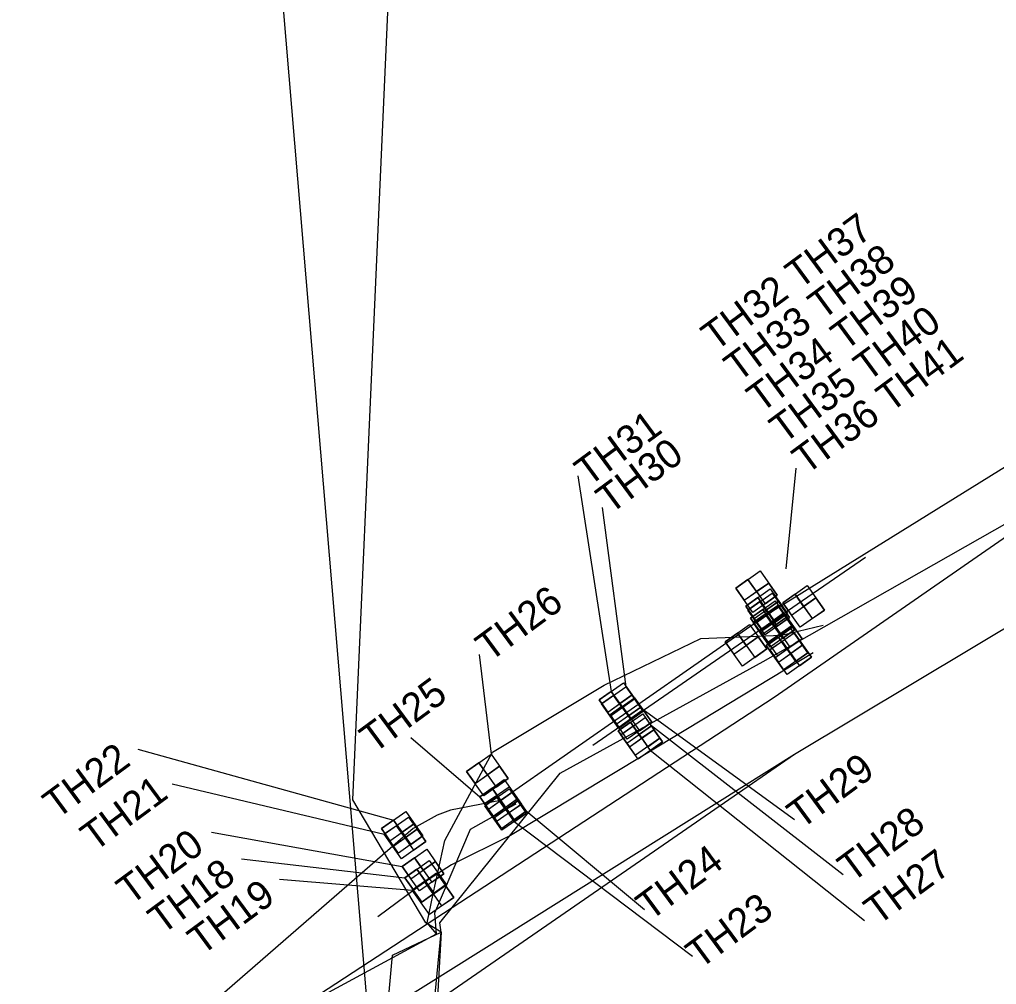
# Model space of a CAD drawing. Extents: x 507915 to 518914, y 880723 to 883087.
# Drawn here: x 509177.3 to 509259.1, y 882249.9 to 882330.6 of the extents above; entities that cross this region are included whole.
import ezdxf

# ---------------------------------------------------------------- set-up
doc = ezdxf.new("R2010")
doc.units = 0
for name, color, linetype in [('Driveway_ep', 7, 'Continuous'), ('GuardrailLt_ep', 7, 'Continuous'), ('GuardrailRt_ep', 7, 'Continuous'), ('Luminaire', 7, 'Continuous'), ('Miscellaneous3', 7, 'Continuous'), ('PavtAsphalt_ep', 7, 'Continuous'), ('PMBikeLane_ep', 7, 'Continuous'), ('PMNORTH_ep', 7, 'Continuous'), ('PoleLight_ep', 7, 'Continuous')]:
    doc.layers.add(name, color=color, linetype=linetype)

msp = doc.modelspace()

# ---------------------------------------------------------------- linework, layer by layer
at = {"layer": 'Driveway_ep'}
msp.add_lwpolyline([(509470.151, 882412.294), (509450.235, 882402.261), (509403.864, 882379.797), (509373.735, 882360.535), (509360.257, 882353.193), (509318.085, 882328.858), (509274.108, 882302.037), (509240.021, 882280.899), (509217.599, 882265.284), (509213.419, 882264.477), (509212.298, 882264.042), (509210.283, 882262.924), (509172.924, 882230.488), (509113.967, 882188.988), (509087.108, 882169.954), (509067.759, 882154.568), (509006.28, 882108.596)], dxfattribs=at)
at = {"layer": 'GuardrailRt_ep'}
for p, q in [((509224.055, 882292.462), (509226.858, 882274.411)), ((509242.3, 882293.092), (509241.454, 882284.664)), ((509226.084, 882289.794), (509228.078, 882274.796)), ((509215.795, 882277.487), (509216.795, 882269.158)), ((509242.196, 882263.663), (509229.521, 882272.862)), ((509246.255, 882259.069), (509230.211, 882271.523)), ((509210.078, 882270.556), (509215.857, 882265.584)), ((509187.249, 882269.577), (509208.641, 882263.643)), ((509248.039, 882255.209), (509230.12, 882269.461)), ((509190.117, 882266.683), (509207.86, 882262.449)), ((509229.625, 882256.117), (509219.745, 882264.387)), ((509233.648, 882252.217), (509218.733, 882263.502)), ((509193.411, 882262.634), (509209.374, 882259.752)), ((509195.914, 882260.382), (509209.579, 882258.809)), ((509199.094, 882258.69), (509210.202, 882257.772))]:
    msp.add_line(p, q, dxfattribs=at)
at = {"layer": 'Luminaire'}
msp.add_lwpolyline([(509209.542, 882030.607), (509208.49, 882117.664), (509208.133, 882156.35), (509208.412, 882184.48), (509208.186, 882227.958), (509206.41, 882248.671), (509195.558, 882377.683), (509191.832, 882422.316), (509185.306, 882558.4)], dxfattribs=at)
at = {"layer": 'Miscellaneous3'}
for points in [[(509130.876, 882181.709), (509131.052, 882184.291), (509136.669, 882194.388), (509176.072, 882223.491), (509242.192, 882269.149), (509301.705, 882304.805), (509379.728, 882350.734), (509420.133, 882372.958), (509456.8, 882391.955), (509476.67, 882399.785)], [(509130.876, 882181.709), (509131.052, 882184.291), (509136.669, 882194.388), (509176.072, 882223.491), (509204.835, 882245.757), (509242.192, 882269.149), (509301.705, 882304.805), (509379.728, 882350.734), (509420.133, 882372.958), (509456.8, 882391.955), (509476.67, 882399.785)]]:
    msp.add_lwpolyline(points, dxfattribs=at)
at = {"layer": 'PavtAsphalt_ep'}
for points in [[(509213.58, 882113.608), (509213.174, 882115.678), (509214.272, 882140.381), (509214.048, 882192.03), (509209.447, 882233.648), (509207.929, 882245.59), (509208.548, 882252.334), (509212.627, 882254.268), (509211.346, 882255.034), (509205.243, 882265.325), (509209.207, 882354.521), (509209.439, 882393.982), (509208.915, 882404.218), (509206.519, 882409.455), (509204.896, 882411.033)], [(509213.58, 882113.608), (509213.912, 882115.528), (509214.707, 882140.609), (509214.384, 882191.99), (509210.495, 882232.364), (509212.627, 882254.268), (509212.516, 882255.039), (509222.591, 882267.569), (509239.558, 882276.92), (509275.893, 882297.556), (509319.517, 882324.511), (509375.22, 882356.185), (509418.494, 882377.58), (509454.448, 882397.183), (509473.499, 882406.553)], [(509064.731, 882160.378), (509118.151, 882196.986), (509178.011, 882233.345), (509198.905, 882246.902), (509212.244, 882254.107), (509211.466, 882255.048), (509211.944, 882257.472), (509212.922, 882261.936), (509216.927, 882269.312), (509226.267, 882274.922), (509234.361, 882278.841), (509241.088, 882279.121), (509244.586, 882279.945)], [(509243.76, 882277.627), (509229.641, 882269.091), (509218.434, 882262.343), (509213.502, 882259.899), (509211.321, 882258.509), (509207.333, 882255.551)], [(509212.244, 882254.107), (509212.093, 882255.886), (509215.065, 882262.887), (509218.012, 882264.523), (509218.889, 882264.999)], [(509212.627, 882254.268), (509211.434, 882232.968), (509214.725, 882192.224), (509214.943, 882140.805), (509214.574, 882115.446), (509213.58, 882113.608), (509219.638, 882063.307)]]:
    msp.add_lwpolyline(points, dxfattribs=at)
at = {"layer": 'PMBikeLane_ep'}
for p, q in [((509237.268, 882283.058), (509239.31, 882284.5)), ((509239.31, 882284.5), (509240.752, 882282.458)), ((509238.289, 882283.779), (509237.268, 882283.058)), ((509237.989, 882282.037), (509240.031, 882283.479)), ((509238.289, 882283.779), (509239.731, 882281.737)), ((509239.01, 882282.758), (509238.289, 882283.779)), ((509240.031, 882283.479), (509239.01, 882282.758)), ((509240.752, 882282.458), (509240.031, 882283.479)), ((509238.71, 882281.016), (509237.268, 882283.058)), ((509237.268, 882283.058), (509237.989, 882282.037)), ((509237.989, 882282.037), (509239.01, 882282.758)), ((509238.105, 882281.537), (509240.147, 882282.979)), ((509238.279, 882281.198), (509240.321, 882282.641)), ((509239.01, 882282.758), (509239.731, 882281.737)), ((509239.01, 882282.758), (509239.01, 882282.758)), ((509240.147, 882282.979), (509241.59, 882280.937)), ((509240.321, 882282.641), (509241.763, 882280.599)), ((509241.212, 882281.82), (509243.255, 882283.262)), ((509242.233, 882282.541), (509241.212, 882281.82)), ((509242.233, 882282.541), (509243.676, 882280.499)), ((509242.955, 882281.52), (509242.233, 882282.541)), ((509243.255, 882283.262), (509244.697, 882281.22)), ((509239.126, 882282.258), (509238.105, 882281.537)), ((509239.3, 882281.92), (509238.279, 882281.198)), ((509238.516, 882280.532), (509240.558, 882281.974)), ((509240.752, 882282.458), (509238.71, 882281.016)), ((509238.826, 882280.516), (509240.869, 882281.958)), ((509239.126, 882282.258), (509240.569, 882280.216)), ((509239.847, 882281.237), (509239.126, 882282.258)), ((509239.3, 882281.92), (509240.742, 882279.877)), ((509240.021, 882280.899), (509239.3, 882281.92)), ((509239.731, 882281.737), (509240.752, 882282.458)), ((509240.869, 882281.958), (509239.847, 882281.237)), ((509240.558, 882281.974), (509242, 882279.932)), ((509241.59, 882280.937), (509240.869, 882281.958)), ((509242.655, 882279.778), (509241.212, 882281.82)), ((509241.212, 882281.82), (509241.934, 882280.799)), ((509241.934, 882280.799), (509243.976, 882282.241)), ((509243.976, 882282.241), (509242.955, 882281.52)), ((509244.697, 882281.22), (509243.976, 882282.241)), ((509239.548, 882279.495), (509238.105, 882281.537)), ((509238.105, 882281.537), (509238.826, 882280.516)), ((509239.721, 882279.156), (509238.279, 882281.198)), ((509238.279, 882281.198), (509239, 882280.177)), ((509239.537, 882281.253), (509238.516, 882280.532)), ((509238.719, 882280.163), (509240.761, 882281.605)), ((509239.74, 882280.884), (509238.719, 882280.163)), ((509238.826, 882280.516), (509239.847, 882281.237)), ((509239, 882280.177), (509241.042, 882281.62)), ((509239, 882280.177), (509240.021, 882280.899)), ((509239.237, 882279.51), (509241.279, 882280.953)), ((509239.537, 882281.253), (509240.979, 882279.211)), ((509240.258, 882280.232), (509239.537, 882281.253)), ((509241.59, 882280.937), (509239.548, 882279.495)), ((509239.74, 882280.884), (509241.182, 882278.842)), ((509240.461, 882279.863), (509239.74, 882280.884)), ((509239.847, 882281.237), (509240.569, 882280.216)), ((509239.847, 882281.237), (509239.847, 882281.237)), ((509241.042, 882281.62), (509240.021, 882280.899)), ((509240.021, 882280.899), (509240.742, 882279.877)), ((509240.021, 882280.899), (509240.021, 882280.899)), ((509241.279, 882280.953), (509240.258, 882280.232)), ((509240.569, 882280.216), (509241.59, 882280.937)), ((509240.761, 882281.605), (509242.203, 882279.563)), ((509241.763, 882280.599), (509241.042, 882281.62)), ((509242, 882279.932), (509241.279, 882280.953)), ((509241.934, 882280.799), (509242.955, 882281.52)), ((509244.697, 882281.22), (509242.655, 882279.778)), ((509242.955, 882281.52), (509243.676, 882280.499)), ((509242.955, 882281.52), (509242.955, 882281.52)), ((509243.676, 882280.499), (509244.697, 882281.22)), ((509239.958, 882278.489), (509238.516, 882280.532)), ((509238.516, 882280.532), (509239.237, 882279.51)), ((509240.161, 882278.121), (509238.719, 882280.163)), ((509238.719, 882280.163), (509239.44, 882279.142)), ((509239.237, 882279.51), (509240.258, 882280.232)), ((509239.346, 882279.421), (509241.388, 882280.863)), ((509240.367, 882280.142), (509239.346, 882279.421)), ((509239.44, 882279.142), (509241.482, 882280.584)), ((509241.763, 882280.599), (509239.721, 882279.156)), ((509240.258, 882280.232), (509240.979, 882279.211)), ((509240.258, 882280.232), (509240.258, 882280.232)), ((509240.367, 882280.142), (509241.81, 882278.1)), ((509241.088, 882279.121), (509240.367, 882280.142)), ((509241.482, 882280.584), (509240.461, 882279.863)), ((509240.742, 882279.877), (509241.763, 882280.599)), ((509241.388, 882280.863), (509242.831, 882278.821)), ((509242.203, 882279.563), (509241.482, 882280.584)), ((509236.393, 882278.558), (509238.435, 882280)), ((509237.414, 882279.279), (509236.393, 882278.558)), ((509237.414, 882279.279), (509238.857, 882277.237)), ((509238.135, 882278.258), (509237.414, 882279.279)), ((509238.435, 882280), (509239.878, 882277.958)), ((509240.788, 882277.379), (509239.346, 882279.421)), ((509239.346, 882279.421), (509240.067, 882278.4)), ((509239.44, 882279.142), (509240.461, 882279.863)), ((509239.815, 882278.243), (509241.857, 882279.686)), ((509242, 882279.932), (509239.958, 882278.489)), ((509240.067, 882278.4), (509242.109, 882279.842)), ((509240.131, 882277.877), (509242.173, 882279.319)), ((509242.203, 882279.563), (509240.161, 882278.121)), ((509240.461, 882279.863), (509241.182, 882278.842)), ((509240.461, 882279.863), (509240.461, 882279.863)), ((509240.979, 882279.211), (509242, 882279.932)), ((509242.109, 882279.842), (509241.088, 882279.121)), ((509241.182, 882278.842), (509242.203, 882279.563)), ((509241.857, 882279.686), (509243.3, 882277.643)), ((509242.831, 882278.821), (509242.109, 882279.842)), ((509242.173, 882279.319), (509243.616, 882277.277)), ((509237.835, 882276.516), (509236.393, 882278.558)), ((509236.393, 882278.558), (509237.114, 882277.537)), ((509237.114, 882277.537), (509239.156, 882278.979)), ((509239.156, 882278.979), (509238.135, 882278.258)), ((509239.878, 882277.958), (509239.156, 882278.979)), ((509240.836, 882278.964), (509239.815, 882278.243)), ((509240.067, 882278.4), (509241.088, 882279.121)), ((509241.152, 882278.598), (509240.131, 882277.877)), ((509240.536, 882277.222), (509242.578, 882278.665)), ((509242.831, 882278.821), (509240.788, 882277.379)), ((509240.836, 882278.964), (509242.279, 882276.922)), ((509241.557, 882277.943), (509240.836, 882278.964)), ((509241.088, 882279.121), (509241.81, 882278.1)), ((509241.088, 882279.121), (509241.088, 882279.121)), ((509241.152, 882278.598), (509242.595, 882276.556)), ((509241.873, 882277.577), (509241.152, 882278.598)), ((509242.578, 882278.665), (509241.557, 882277.943)), ((509241.81, 882278.1), (509242.831, 882278.821)), ((509243.3, 882277.643), (509242.578, 882278.665)), ((509237.114, 882277.537), (509238.135, 882278.258)), ((509239.878, 882277.958), (509237.835, 882276.516)), ((509238.135, 882278.258), (509238.857, 882277.237)), ((509238.135, 882278.258), (509238.135, 882278.258)), ((509238.857, 882277.237), (509239.878, 882277.958)), ((509241.257, 882276.201), (509239.815, 882278.243)), ((509239.815, 882278.243), (509240.536, 882277.222)), ((509241.574, 882275.834), (509240.131, 882277.877)), ((509240.131, 882277.877), (509240.852, 882276.855)), ((509240.536, 882277.222), (509241.557, 882277.943)), ((509240.852, 882276.855), (509242.895, 882278.298)), ((509243.3, 882277.643), (509241.257, 882276.201)), ((509241.557, 882277.943), (509242.279, 882276.922)), ((509241.557, 882277.943), (509241.557, 882277.943)), ((509242.895, 882278.298), (509241.873, 882277.577)), ((509242.279, 882276.922), (509243.3, 882277.643)), ((509243.616, 882277.277), (509242.895, 882278.298)), ((509240.852, 882276.855), (509241.873, 882277.577)), ((509243.616, 882277.277), (509241.574, 882275.834)), ((509241.873, 882277.577), (509242.595, 882276.556)), ((509241.873, 882277.577), (509241.873, 882277.577)), ((509242.595, 882276.556), (509243.616, 882277.277)), ((509225.837, 882273.69), (509227.879, 882275.132)), ((509226.858, 882274.411), (509225.837, 882273.69)), ((509226.036, 882273.354), (509228.078, 882274.796)), ((509226.858, 882274.411), (509228.3, 882272.369)), ((509227.579, 882273.39), (509226.858, 882274.411)), ((509227.879, 882275.132), (509229.321, 882273.09)), ((509228.078, 882274.796), (509229.52, 882272.754)), ((509227.279, 882271.648), (509225.837, 882273.69)), ((509225.837, 882273.69), (509226.558, 882272.669)), ((509227.057, 882274.075), (509226.036, 882273.354)), ((509226.558, 882272.669), (509228.6, 882274.111)), ((509226.757, 882272.333), (509228.799, 882273.775)), ((509226.758, 882272.44), (509228.8, 882273.883)), ((509227.057, 882274.075), (509228.499, 882272.033)), ((509227.778, 882273.054), (509227.057, 882274.075)), ((509228.6, 882274.111), (509227.579, 882273.39)), ((509228.799, 882273.775), (509227.778, 882273.054)), ((509229.321, 882273.09), (509228.6, 882274.111)), ((509229.52, 882272.754), (509228.799, 882273.775)), ((509228.8, 882273.883), (509230.242, 882271.841)), ((509227.478, 882271.312), (509226.036, 882273.354)), ((509226.036, 882273.354), (509226.757, 882272.333)), ((509226.558, 882272.669), (509227.579, 882273.39)), ((509226.757, 882272.333), (509227.778, 882273.054)), ((509227.779, 882273.162), (509226.758, 882272.44)), ((509229.321, 882273.09), (509227.279, 882271.648)), ((509229.52, 882272.754), (509227.478, 882271.312)), ((509227.479, 882271.419), (509229.521, 882272.862)), ((509227.579, 882273.39), (509228.3, 882272.369)), ((509227.579, 882273.39), (509227.579, 882273.39)), ((509227.778, 882273.054), (509228.499, 882272.033)), ((509227.778, 882273.054), (509227.778, 882273.054)), ((509227.779, 882273.162), (509229.221, 882271.119)), ((509228.5, 882272.14), (509227.779, 882273.162)), ((509228.3, 882272.369), (509229.321, 882273.09)), ((509228.499, 882272.033), (509229.52, 882272.754)), ((509229.521, 882272.862), (509228.5, 882272.14)), ((509230.242, 882271.841), (509229.521, 882272.862)), ((509228.2, 882270.398), (509226.758, 882272.44)), ((509226.758, 882272.44), (509227.479, 882271.419)), ((509227.448, 882271.101), (509229.49, 882272.544)), ((509227.479, 882271.419), (509228.5, 882272.14)), ((509227.657, 882270.782), (509229.699, 882272.224)), ((509228.5, 882272.14), (509229.221, 882271.119)), ((509228.5, 882272.14), (509228.5, 882272.14)), ((509229.49, 882272.544), (509230.932, 882270.501)), ((509229.699, 882272.224), (509231.141, 882270.182)), ((509228.469, 882271.822), (509227.448, 882271.101)), ((509228.89, 882269.059), (509227.448, 882271.101)), ((509227.448, 882271.101), (509228.169, 882270.08)), ((509228.678, 882271.503), (509227.657, 882270.782)), ((509228.169, 882270.08), (509230.211, 882271.523)), ((509230.242, 882271.841), (509228.2, 882270.398)), ((509228.378, 882269.761), (509230.42, 882271.203)), ((509228.469, 882271.822), (509229.911, 882269.78)), ((509229.19, 882270.801), (509228.469, 882271.822)), ((509228.678, 882271.503), (509230.12, 882269.461)), ((509229.399, 882270.482), (509228.678, 882271.503)), ((509230.211, 882271.523), (509229.19, 882270.801)), ((509229.221, 882271.119), (509230.242, 882271.841)), ((509230.42, 882271.203), (509229.399, 882270.482)), ((509230.932, 882270.501), (509230.211, 882271.523)), ((509231.141, 882270.182), (509230.42, 882271.203)), ((509229.099, 882268.74), (509227.657, 882270.782)), ((509227.657, 882270.782), (509228.378, 882269.761)), ((509228.169, 882270.08), (509229.19, 882270.801)), ((509228.378, 882269.761), (509229.399, 882270.482)), ((509230.932, 882270.501), (509228.89, 882269.059)), ((509229.19, 882270.801), (509229.911, 882269.78)), ((509229.19, 882270.801), (509229.19, 882270.801)), ((509229.399, 882270.482), (509230.12, 882269.461)), ((509229.399, 882270.482), (509229.399, 882270.482)), ((509229.911, 882269.78), (509230.932, 882270.501)), ((509231.141, 882270.182), (509229.099, 882268.74)), ((509230.12, 882269.461), (509231.141, 882270.182)), ((509214.753, 882267.716), (509216.795, 882269.158)), ((509216.795, 882269.158), (509218.237, 882267.116)), ((509215.774, 882268.437), (509214.753, 882267.716)), ((509215.474, 882266.695), (509217.516, 882268.137)), ((509215.774, 882268.437), (509217.216, 882266.395)), ((509216.495, 882267.416), (509215.774, 882268.437)), ((509217.516, 882268.137), (509216.495, 882267.416)), ((509218.237, 882267.116), (509217.516, 882268.137)), ((509216.195, 882265.674), (509214.753, 882267.716)), ((509214.753, 882267.716), (509215.474, 882266.695)), ((509215.474, 882266.695), (509216.495, 882267.416)), ((509215.857, 882265.584), (509217.899, 882267.026)), ((509218.237, 882267.116), (509216.195, 882265.674)), ((509216.495, 882267.416), (509217.216, 882266.395)), ((509216.495, 882267.416), (509216.495, 882267.416)), ((509217.216, 882266.395), (509218.237, 882267.116)), ((509217.899, 882267.026), (509219.341, 882264.984)), ((509216.878, 882266.305), (509215.857, 882265.584)), ((509216.261, 882264.987), (509218.303, 882266.429)), ((509216.27, 882264.823), (509218.312, 882266.265)), ((509216.878, 882266.305), (509218.32, 882264.263)), ((509217.599, 882265.284), (509216.878, 882266.305)), ((509218.303, 882266.429), (509219.745, 882264.387)), ((509218.312, 882266.265), (509219.754, 882264.223)), ((509217.299, 882263.542), (509215.857, 882265.584)), ((509215.857, 882265.584), (509216.578, 882264.563)), ((509217.282, 882265.708), (509216.261, 882264.987)), ((509217.291, 882265.544), (509216.27, 882264.823)), ((509216.578, 882264.563), (509218.62, 882266.005)), ((509216.982, 882263.966), (509219.024, 882265.408)), ((509217.282, 882265.708), (509218.724, 882263.666)), ((509218.003, 882264.687), (509217.282, 882265.708)), ((509217.291, 882265.544), (509218.733, 882263.502)), ((509218.012, 882264.523), (509217.291, 882265.544)), ((509218.62, 882266.005), (509217.599, 882265.284)), ((509219.024, 882265.408), (509218.003, 882264.687)), ((509219.341, 882264.984), (509218.62, 882266.005)), ((509219.745, 882264.387), (509219.024, 882265.408)), ((509217.703, 882262.945), (509216.261, 882264.987)), ((509216.261, 882264.987), (509216.982, 882263.966)), ((509217.712, 882262.781), (509216.27, 882264.823)), ((509216.27, 882264.823), (509216.991, 882263.802)), ((509216.578, 882264.563), (509217.599, 882265.284)), ((509216.982, 882263.966), (509218.003, 882264.687)), ((509216.991, 882263.802), (509219.033, 882265.244)), ((509219.341, 882264.984), (509217.299, 882263.542)), ((509217.599, 882265.284), (509218.32, 882264.263)), ((509217.599, 882265.284), (509217.599, 882265.284)), ((509218.003, 882264.687), (509218.724, 882263.666)), ((509218.003, 882264.687), (509218.003, 882264.687)), ((509219.033, 882265.244), (509218.012, 882264.523)), ((509218.32, 882264.263), (509219.341, 882264.984)), ((509219.754, 882264.223), (509219.033, 882265.244)), ((509207.62, 882262.922), (509209.662, 882264.364)), ((509207.86, 882262.449), (509209.902, 882263.891)), ((509209.662, 882264.364), (509211.104, 882262.322)), ((509209.902, 882263.891), (509211.344, 882261.849)), ((509216.991, 882263.802), (509218.012, 882264.523)), ((509219.745, 882264.387), (509217.703, 882262.945)), ((509219.754, 882264.223), (509217.712, 882262.781)), ((509218.012, 882264.523), (509218.733, 882263.502)), ((509218.012, 882264.523), (509218.012, 882264.523)), ((509218.724, 882263.666), (509219.745, 882264.387)), ((509218.733, 882263.502), (509219.754, 882264.223)), ((509208.641, 882263.643), (509207.62, 882262.922)), ((509209.062, 882260.88), (509207.62, 882262.922)), ((509207.62, 882262.922), (509208.341, 882261.901)), ((509208.881, 882263.17), (509207.86, 882262.449)), ((509208.341, 882261.901), (509210.383, 882263.343)), ((509208.641, 882263.643), (509210.083, 882261.601)), ((509209.362, 882262.622), (509208.641, 882263.643)), ((509208.881, 882263.17), (509210.323, 882261.128)), ((509209.602, 882262.149), (509208.881, 882263.17)), ((509210.383, 882263.343), (509209.362, 882262.622)), ((509211.104, 882262.322), (509210.383, 882263.343)), ((509209.302, 882260.407), (509207.86, 882262.449)), ((509207.86, 882262.449), (509208.581, 882261.428)), ((509208.341, 882261.901), (509209.362, 882262.622)), ((509208.581, 882261.428), (509210.623, 882262.87)), ((509208.581, 882261.428), (509209.602, 882262.149)), ((509211.104, 882262.322), (509209.062, 882260.88)), ((509209.362, 882262.622), (509210.083, 882261.601)), ((509209.362, 882262.622), (509209.362, 882262.622)), ((509210.623, 882262.87), (509209.602, 882262.149)), ((509209.602, 882262.149), (509210.323, 882261.128)), ((509209.602, 882262.149), (509209.602, 882262.149)), ((509210.083, 882261.601), (509211.104, 882262.322)), ((509211.344, 882261.849), (509210.623, 882262.87)), ((509211.344, 882261.849), (509209.302, 882260.407)), ((509210.323, 882261.128), (509211.344, 882261.849)), ((509209.374, 882259.752), (509211.416, 882261.195)), ((509210.395, 882260.473), (509209.374, 882259.752)), ((509210.395, 882260.473), (509211.837, 882258.431)), ((509211.116, 882259.452), (509210.395, 882260.473)), ((509211.416, 882261.195), (509212.858, 882259.152)), ((509210.816, 882257.71), (509209.374, 882259.752)), ((509209.374, 882259.752), (509210.095, 882258.731)), ((509209.579, 882258.809), (509211.621, 882260.251)), ((509210.095, 882258.731), (509212.137, 882260.174)), ((509212.137, 882260.174), (509211.116, 882259.452)), ((509211.621, 882260.251), (509213.063, 882258.209)), ((509212.858, 882259.152), (509212.137, 882260.174)), ((509210.6, 882259.53), (509209.579, 882258.809)), ((509210.095, 882258.731), (509211.116, 882259.452)), ((509210.202, 882257.772), (509212.244, 882259.214)), ((509210.3, 882257.787), (509212.342, 882259.23)), ((509210.6, 882259.53), (509212.042, 882257.488)), ((509211.321, 882258.509), (509210.6, 882259.53)), ((509212.858, 882259.152), (509210.816, 882257.71)), ((509211.116, 882259.452), (509211.837, 882258.431)), ((509211.116, 882259.452), (509211.116, 882259.452)), ((509212.342, 882259.23), (509211.321, 882258.509)), ((509211.837, 882258.431), (509212.858, 882259.152)), ((509212.244, 882259.214), (509213.686, 882257.172)), ((509213.063, 882258.209), (509212.342, 882259.23)), ((509211.021, 882256.766), (509209.579, 882258.809)), ((509209.579, 882258.809), (509210.3, 882257.787)), ((509211.223, 882258.493), (509210.202, 882257.772)), ((509210.3, 882257.787), (509211.321, 882258.509)), ((509210.923, 882256.751), (509212.965, 882258.193)), ((509213.063, 882258.209), (509211.021, 882256.766)), ((509211.223, 882258.493), (509212.665, 882256.451)), ((509211.944, 882257.472), (509211.223, 882258.493)), ((509211.321, 882258.509), (509212.042, 882257.488)), ((509211.321, 882258.509), (509211.321, 882258.509)), ((509212.965, 882258.193), (509211.944, 882257.472)), ((509212.042, 882257.488), (509213.063, 882258.209)), ((509213.686, 882257.172), (509212.965, 882258.193)), ((509211.644, 882255.73), (509210.202, 882257.772)), ((509210.202, 882257.772), (509210.923, 882256.751)), ((509210.923, 882256.751), (509211.944, 882257.472)), ((509211.944, 882257.472), (509212.665, 882256.451)), ((509211.944, 882257.472), (509211.944, 882257.472)), ((509213.686, 882257.172), (509211.644, 882255.73)), ((509212.665, 882256.451), (509213.686, 882257.172))]:
    msp.add_line(p, q, dxfattribs=at)
at = {"layer": 'PMNORTH_ep'}
msp.add_lwpolyline([(509225.328, 882269.921), (509240.258, 882280.232), (509248.137, 882285.633)], dxfattribs=at)
at = {"layer": 'PoleLight_ep'}
msp.add_lwpolyline([(509066.189, 882157.001), (509063.703, 882160.81), (509096.648, 882182.649), (509173.39, 882230.11), (509240.494, 882273.931), (509264.924, 882290.866), (509276.298, 882299.742), (509283.119, 882303.889), (509320.524, 882322.387), (509376.961, 882358.251), (509415.581, 882380.911), (509454.186, 882398.171), (509477.227, 882409.319)], dxfattribs=at)

# ---------------------------------------------------------------- texts
at = {"layer": 'GuardrailLt_ep'}
for s, p in [('TH32 TH37', (509235.56, 882302.812)), ('TH33 TH38', (509237.462, 882300.233)), ('TH34 TH39', (509239.365, 882297.654)), ('TH35 TH40', (509241.268, 882295.074)), ('TH36 TH41', (509243.171, 882292.495)), ('TH31', (509224.957, 882291.495)), ('TH30', (509226.756, 882289.177)), ('TH26', (509216.678, 882276.821)), ('TH25', (509206.98, 882269.147)), ('TH22', (509180.466, 882263.66)), ('TH29', (509242.737, 882262.804)), ('TH21', (509183.614, 882260.927)), ('TH28', (509246.969, 882258.343)), ('TH20', (509186.628, 882256.458)), ('TH24', (509230.098, 882255.138)), ('TH27', (509249.166, 882254.761)), ('TH18', (509189.259, 882253.988)), ('TH19', (509192.577, 882252.251)), ('TH23', (509234.264, 882251.11))]:
    msp.add_text(s, height=2.4, rotation=36.41746, dxfattribs=at).set_placement(p)

doc.saveas('drawing.dxf')
